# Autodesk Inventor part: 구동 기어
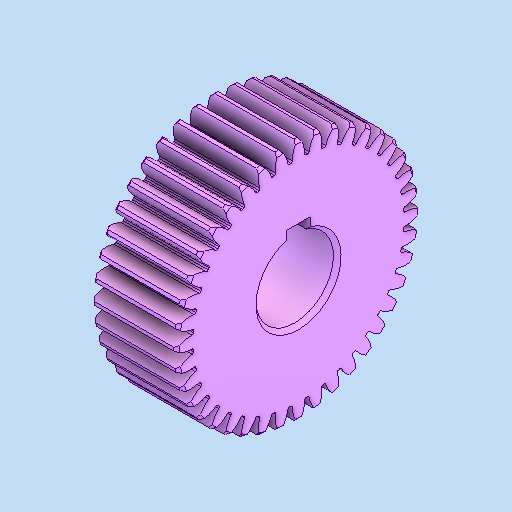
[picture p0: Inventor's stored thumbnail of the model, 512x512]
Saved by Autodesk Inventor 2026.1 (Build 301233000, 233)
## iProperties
Created: 2025-11
Part Number: 구동 기어
Material: 강철, 합금
Document SubType Name: Modeling
Designer: PC-30
Density: 7.73 g/cm^3
Appearance: 기본값
Author: jhkim
Sending System: Autodesk Inventor 2026
Preprocessor: ST-DEVELOPER v20.1
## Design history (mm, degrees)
feature "솔리드1"
node "솔리드2"
